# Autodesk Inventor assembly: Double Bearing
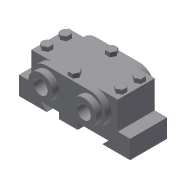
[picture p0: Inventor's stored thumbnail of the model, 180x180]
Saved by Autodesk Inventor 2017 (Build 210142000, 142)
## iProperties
Shininess: 64.0
Length Units: 11269
Angle Units: 11279
Time Units: 11290
Mass Units: 11283
Length Display Precision: 3
Angle Display Precision: 2
Created: 2002-02
Part Number: Double Bearing
Document SubType Name: Assembly
Designer: ***
Density: 0.0
Volumn: 0.0
Area: 0.0
PropertySet Name: Model Information
Control State: 0
Master: False
Checked Out: False
Author: ***
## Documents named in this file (5)
- D:\KAVITA\Autodesk Inventor_ 2016 Project_Kavita\Inventor_Part Files\Inventor_2016_Exr\c11_inv_2016_exr\c11_Inv\c11_exr01_inv\Double Bearing Assembly\Double Bearing.iam
- D:\KAVITA\Autodesk Inventor_ 2016 Project_Kavita\Inventor_Part Files\Inventor_2016_Exr\c11_inv_2016_exr\c11_Inv\c11_exr01_inv\Double Bearing Assembly\Base.ipt
- D:\KAVITA\Autodesk Inventor_ 2016 Project_Kavita\Inventor_Part Files\Inventor_2016_Exr\c11_inv_2016_exr\c11_Inv\c11_exr01_inv\Double Bearing Assembly\Cap.ipt
- D:\KAVITA\Autodesk Inventor_ 2016 Project_Kavita\Inventor_Part Files\Inventor_2016_Exr\c11_inv_2016_exr\c11_Inv\c11_exr01_inv\Double Bearing Assembly\Bushing.ipt
- D:\KAVITA\Autodesk Inventor_ 2016 Project_Kavita\Inventor_Part Files\Inventor_2016_Exr\c11_inv_2016_exr\c11_Inv\c11_exr01_inv\Double Bearing Assembly\Bolt.ipt
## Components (10 placed, 4 different names)
1. Base:1 — Insert:1, Insert:2
2. Cap:1 — Insert:1, Insert:2, Insert:3, Insert:4, Insert:5, Insert:6
3. Bushing:1 — Insert:3
4. Bushing:2 — Insert:4
5. Bolt:1 — Insert:5
6. Bolt:6
7. Bolt:7
8. Bolt:8
9. Bolt:5 — Insert:6
10. Bolt:9
## Component patterns: Component Pattern 1 (4 elements), Component Pattern 2 (2 elements)
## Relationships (6: Insert 6)
- Insert:1: Base:1 ↔ Cap:1
- Insert:2: Base:1 ↔ Cap:1
- Insert:3: Cap:1 ↔ Bushing:1
- Insert:4: Cap:1 ↔ Bushing:2
- Insert:5: Cap:1 ↔ Bolt:1
- Insert:6: Cap:1 ↔ Bolt:5
